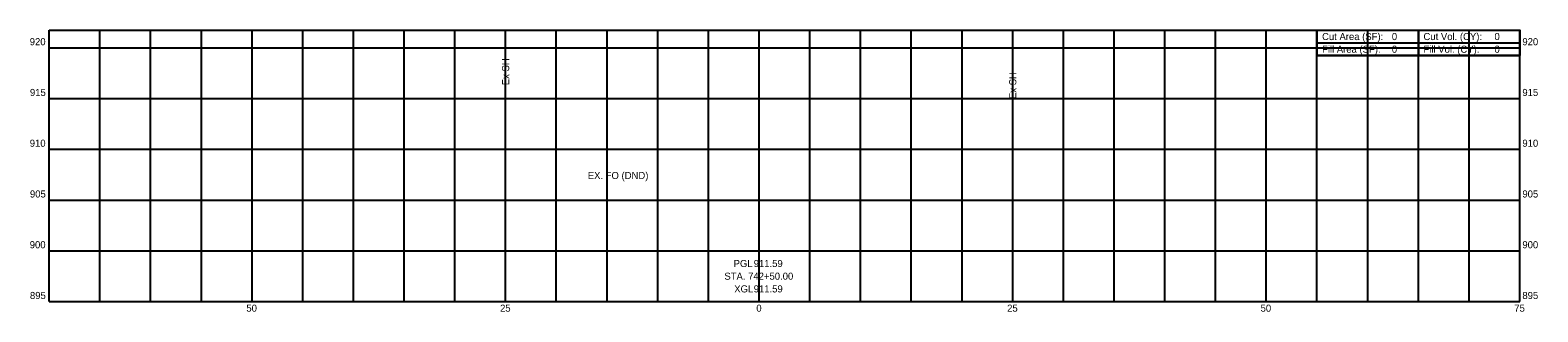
# Model space of a CAD drawing. Extents: x -72 to 77, y 894 to 922.
import ezdxf

# ---------------------------------------------------------------- set-up
doc = ezdxf.new("R2010")
doc.units = 0
for name, color, linetype in [('Default', 7, 'Continuous'), ('RW_X_Esmt_SH', 7, 'Continuous'), ('SH_Data', 7, 'Continuous'), ('SH_Major_Grid_Line', 7, 'Continuous'), ('SH_Masking', 7, 'Continuous'), ('SH_Text', 7, 'Continuous')]:
    doc.layers.add(name, color=color, linetype=linetype)

msp = doc.modelspace()

# ---------------------------------------------------------------- linework, layer by layer
at = {"layer": 'Default'}
msp.add_circle((75, 921.73), 0.000417, dxfattribs=at)
msp.add_circle((75, 921.73), 0.000417, dxfattribs=at)
msp.add_circle((75, 921.73), 0.000417, dxfattribs=at)
msp.add_circle((75, 921.73), 0.000417, dxfattribs=at)
msp.add_circle((75, 921.73), 0.000417, dxfattribs=at)
msp.add_circle((75, 921.73), 0.000417, dxfattribs=at)
msp.add_circle((75, 921.73), 0.000417, dxfattribs=at)
msp.add_circle((75, 921.73), 0.000417, dxfattribs=at)
msp.add_circle((75, 921.73), 0.000417, dxfattribs=at)
msp.add_circle((75, 921.73), 0.000417, dxfattribs=at)
msp.add_circle((75, 921.73), 0.000417, dxfattribs=at)
msp.add_circle((75, 921.73), 0.000417, dxfattribs=at)
at = {"layer": 'RW_X_Esmt_SH'}
for p, q in [((-25, 910.81), (-25, 915.81)), ((25, 909.45), (25, 914.45))]:
    msp.add_line(p, q, dxfattribs=at)
at = {"layer": 'SH_Data'}
for p, q in [((55, 921.73), (75, 921.73)), ((55, 921.73), (55, 919.23)), ((65, 921.73), (65, 919.23)), ((75, 921.73), (75, 919.23)), ((55, 920.48), (75, 920.48)), ((55, 919.23), (75, 919.23))]:
    msp.add_line(p, q, dxfattribs=at)
at = {"layer": 'SH_Major_Grid_Line'}
for p, q in [((-70, 921.73), (75, 921.73)), ((-70, 895), (-70, 921.73)), ((-65, 895), (-65, 921.73)), ((-60, 895), (-60, 921.73)), ((-55, 895), (-55, 921.73)), ((-50, 895), (-50, 921.73)), ((-45, 895), (-45, 921.73)), ((-40, 895), (-40, 921.73)), ((-35, 895), (-35, 921.73)), ((-30, 895), (-30, 921.73)), ((-25, 895), (-25, 921.73)), ((-20, 895), (-20, 921.73)), ((-15, 895), (-15, 921.73)), ((-10, 895), (-10, 921.73)), ((-5, 895), (-5, 921.73)), ((0, 895), (0, 921.73)), ((5, 895), (5, 921.73)), ((10, 895), (10, 921.73)), ((15, 895), (15, 921.73)), ((20, 895), (20, 921.73)), ((25, 895), (25, 921.73)), ((30, 895), (30, 921.73)), ((35, 895), (35, 921.73)), ((40, 895), (40, 921.73)), ((45, 895), (45, 921.73)), ((50, 895), (50, 921.73)), ((55, 895), (55, 921.73)), ((60, 895), (60, 921.73)), ((65, 895), (65, 921.73)), ((70, 895), (70, 921.73)), ((75, 895), (75, 921.73)), ((-70, 920), (75, 920)), ((-70, 915), (75, 915)), ((-70, 910), (75, 910)), ((-70, 905), (75, 905)), ((-70, 900), (75, 900)), ((-70, 895), (75, 895))]:
    msp.add_line(p, q, dxfattribs=at)
at = {"layer": 'SH_Masking'}
msp.add_lwpolyline([(55, 921.73), (75, 921.73), (75, 919.23), (55, 919.23)], close=True, dxfattribs=at)

# ---------------------------------------------------------------- texts
at = {"layer": 'RW_X_Esmt_SH'}
for p in [(-24.65, 916.31), (25.35, 914.95)]:
    msp.add_text('Ex SH', height=0.7, rotation=90, dxfattribs=at).set_placement(p)
at = {"layer": 'SH_Text'}
for s, p in [('920', (-71.92, 920.25)), ('Cut Area (SF):', (55.5, 920.76)), ('Fill Area (SF):', (55.5, 919.51)), ('0', (62.38, 920.76)), ('0', (62.38, 919.51)), ('Cut Vol. (CY):', (65.5, 920.76)), ('Fill Vol. (CY):', (65.5, 919.51)), ('0', (72.5, 920.76)), ('0', (72.5, 919.51)), ('920', (75.25, 920.25)), ('915', (-71.9, 915.25)), ('915', (75.25, 915.25)), ('910', (-71.92, 910.25)), ('910', (75.25, 910.25)), ('EX. FO (DND)', (-16.9, 907.07)), ('905', (-71.9, 905.25)), ('905', (75.25, 905.25)), ('900', (-71.92, 900.25)), ('900', (75.25, 900.25)), ('PGL ', (-2.52, 898.4)), ('911.59', (-0.54, 898.4)), ('STA. 742+50.00', (-3.43, 897.15)), ('XGL ', (-2.46, 895.9)), ('911.59', (-0.54, 895.9)), ('895', (-71.9, 895.25)), ('895', (75.25, 895.25)), ('50', (-50.56, 894)), ('25', (-25.55, 894)), ('0', (-0.28, 894)), ('25', (24.45, 894)), ('50', (49.44, 894)), ('75', (74.45, 894))]:
    msp.add_text(s, height=0.7, dxfattribs=at).set_placement(p)

doc.saveas('drawing.dxf')
